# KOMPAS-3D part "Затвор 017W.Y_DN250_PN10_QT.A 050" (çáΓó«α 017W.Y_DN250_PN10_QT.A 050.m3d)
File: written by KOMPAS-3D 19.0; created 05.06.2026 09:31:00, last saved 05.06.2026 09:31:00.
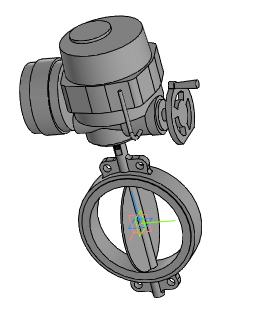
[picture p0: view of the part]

Document properties: Автор: Энергия; Полное имя файла: ..\..\..\3d для проектировщиков\x.x Тип 017W.Y(S) Затвор дисковый поворотный межфланцевый\Затвор 017W.Y(S)_DN32-DN1200_QT.A_MT903.A\Затвор 017W.Y_DN250_PN10_QT.A 050.a3d

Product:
- Part/product: Затвор 017W.Y_DN250_PN10_QT.A 050
    Масса: 132.286

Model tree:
1. Операция без истории:1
